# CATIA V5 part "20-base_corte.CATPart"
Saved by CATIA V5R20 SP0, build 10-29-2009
Part number: 20-base_corte
Revision: ANY
Definition: UNKNOWN
Nomenclature: 20-base_corte
Source: Unknown
Bounding box of the stored display mesh (mm): x -24 to 106, y -29 to 29, z 0 to 22
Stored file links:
  C:\Users\Utente\Desktop\IO LAVORO\3D X SITO CF\CUMSA\3D files CX.013058\CX 013058\20-base_corte.CATPart
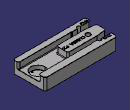
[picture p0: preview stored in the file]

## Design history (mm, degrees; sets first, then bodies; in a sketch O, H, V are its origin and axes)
Body1 "Chaflán24" (main body)
  Solid1: solid without history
